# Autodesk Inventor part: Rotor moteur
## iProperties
Created: 2002-05
Part Number: Rotor moteur
Material: Par défaut
Document SubType Name: Modélisation
Designer: Flavien MARTY
Control State: 0
Master: False
Checked Out: False
Shininess: 20.0
Length Units: 11269
Angle Units: 11279
Time Units: 11290
Mass Units: 11283
Length Display Precision: 3
Angle Display Precision: 2
Compacted: True
Density: 0.0
Volumn: 0.0
Area: 0.0
PropertySet Name: Model Information
Author: Flavien MARTY
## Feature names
1. Extrusion1
2. Chanfrein1 [Chamfer]
